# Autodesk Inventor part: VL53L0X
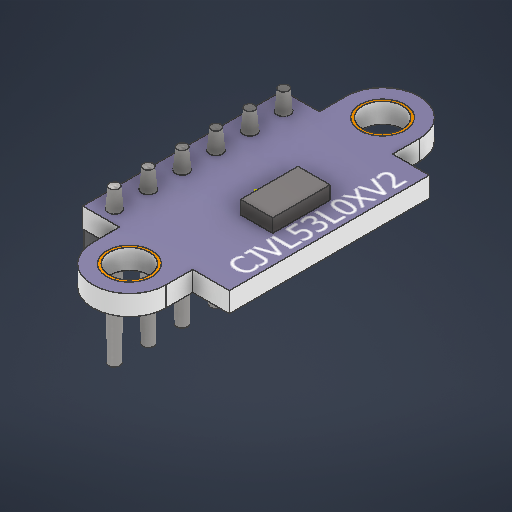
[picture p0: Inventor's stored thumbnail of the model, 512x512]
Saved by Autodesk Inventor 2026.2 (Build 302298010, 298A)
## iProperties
Created: 2026-04
Part Number: VL53L0X
Material: PPS 플라스틱
Document SubType Name: Modeling
Designer: work
Density: 1.637 g/cm^3
Appearance: 매끄러움 - 흰색
Author: work
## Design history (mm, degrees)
sketch "스케치1"
  geometry: L1 (-5.5, 7.5)-(5.5, 7.5); L2 (5.5, 7.5)-(5.5, -7.5); L3 (5.5, -7.5)-(-5.5, -7.5); L4 (-5.5, -7.5)-(-5.5, 7.5); L5 (-5.5, 7.5)-(5.5, -7.5); L6 (5.5, 7.5)-(-5.5, -7.5); L7 (0, 9.5)-(0, -9.5); L8 (0, 9.5)-(0, -9.5); L9 (-2.75, 9.5)-(-2.75, -9.5); L10 (2.75, -9.5)-(2.75, 9.5); C1 r 1.5 at (0, 9.5); C2 r 1.5 at (0, -9.5); A1 r 2.75 centre (0, 9.5) between (2.75, 9.5) and (-2.75, 9.5); A2 r 2.75 centre (0, -9.5) between (-2.75, -9.5) and (2.75, -9.5); 6 further points
  constraints: 22 end point, 6 midpoint, 4 centre point, 4 equal length, 4 point on circle, 4 tangent, 2 coincident, 1 horizontal, 1 perpendicular, 1 vertical
  dimensions: "d0" = 11 distance of L2.end L3.end; "d1" = 15 distance of L1.end L2.end; "d2" = 19 distance of L7.start L7.end; "d3" = 5.5 diameter of A2; "d4" = 3 diameter of C1; "d5" = 3 diameter of C2
extrude "돌출1" new body sketch "스케치1" distance "d6" = 1.5; taper "d7" = 0 deg
sketch "스케치2"
  geometry: L1 (5.5, -7.5)-(5.5, 7.5) reference; L2 (5.5, 0)-(-5.5, 0); L3 (-5.5, 7.5)-(-5.5, -7.5) reference; L4 (3.4, -2.15)-(1, -2.15); L5 (1, -2.15)-(1, 2.15); L6 (1, 2.15)-(3.4, 2.15); L7 (3.4, 2.15)-(3.4, -2.15); L8 (3.4, -2.15)-(1, 2.15); L9 (1, -2.15)-(3.4, 2.15); 2 further points
  constraints: 14 end point, 4 midpoint, 2 parallel, 1 horizontal, 1 perpendicular, 1 point on line
  dimensions: "d8" = 2.4 distance of L5.end L6.end; "d9" = 4.3 distance of L4.end L5.end; "d10" = 4.5 distance between parallel lines of L1 L5
extrude "돌출2" join sketch "스케치2" distance "d11" = 1; taper "d12" = 0 deg
sketch "스케치3"
  geometry: L1 (0, 0)-(-5.5, 0); L2 (-5.5, -7.5)-(-5.5, 7.5) reference; L3 (-3.1, 7.45)-(-5.5, 7.45); L4 (-5.5, 7.45)-(-5.5, -7.45); L5 (-5.5, -7.45)-(-3.1, -7.45); L6 (-3.1, -7.45)-(-3.1, 7.45); L7 (-3.1, 7.45)-(-5.5, -7.45); L8 (-5.5, 7.45)-(-3.1, -7.45); L9 (-5.45, -7.45)-(-5.45, 7.45); 2 further points
  constraints: 16 end point, 4 point on line, 3 midpoint, 2 parallel, 2 perpendicular, 1 horizontal
  dimensions: "d13" = 2.4 distance of L4.end L5.end; "d14" = 14.9 distance of L5.end L3.start; "d17" = 0.05 distance between parallel lines of L2 L9
extrude "돌출3" join sketch "스케치3" distance "d15" = 1.5; taper "d16" = 0 deg
sketch "스케치4"
  geometry: L1 (1, 2.15)-(3.4, 2.15) reference; L2 (3.4, 2.15)-(3.4, -2.15) reference; L3 (3.4, -2.15)-(1, -2.15) reference; L4 (1, -2.15)-(1, 2.15) reference; L5 (2.75, -9.5)-(2.75, -7.5) reference; L6 (2.75, -7.5)-(5.5, -7.5) reference; L7 (5.5, -7.5)-(5.5, 7.5) reference; L8 (5.5, 7.5)-(2.75, 7.5) reference; L9 (2.75, 7.5)-(2.75, 9.5) reference; L10 (-2.75, 9.5)-(-2.75, 7.5) reference; L11 (-2.75, 7.5)-(-5.5, 7.5) reference; L12 (-5.5, 7.5)-(-5.5, -7.5) reference; L13 (-5.5, -7.5)-(-2.75, -7.5) reference; L14 (-2.75, -7.5)-(-2.75, -9.5) reference; C1 r 1.5 at (0, 9.5) reference; C2 r 1.5 at (0, -9.5) reference; C3 r 1.7 at (0, 9.5); C4 r 1.7 at (0, -9.5); A1 r 2.75 centre (0, -9.5) between (-2.75, -9.5) and (2.75, -9.5) reference; A2 r 2.75 centre (0, 9.5) between (2.75, 9.5) and (-2.75, 9.5) reference; 1 further point
  constraints: 2 centre point, 2 coincident
  dimensions: "d18" = 0.2 radial gap between concentric circles of C3 C1; "d19" = 0.2 radial gap between concentric circles of C4 C2
feature "표식1" sketch "스케치4"
sketch "스케치5"
  geometry: L1 (-3.1, 2.05)-(-3.1, 16.95) reference; L2 (-5.5, 2)-(-2.75, 2) reference; L3 (-4.125, 2)-(-4.125, 17); L4 (-2.75, 17)-(-5.5, 17) reference; C1 r 0.5 at (-4.125, 3); C2 r 0.5 at (-4.125, 5.54); C3 r 0.5 at (-4.125, 8.08); C4 r 0.5 at (-4.125, 10.62); C5 r 0.5 at (-4.125, 13.16); C6 r 0.5 at (-4.125, 15.7); 1 further point
  constraints: 6 centre point, 2 end point, 2 midpoint, 1 point on line, 1 vertical, 10 other
  dimensions: "d20" = 1 distance from line of L2 C1.centre; "d23" = 2.54 distance of C1.centre C2.centre; "d28" = 1 diameter of C1
  node "스케치 - 직사각형 패턴1" dims "d23" = 2.54, "d26" = 10
extrude "돌출4" join sketch "스케치5" distance "d29" = 1.5; taper "d30" = -5 deg
extrude "돌출5" join sketch "스케치5" distance "d31" = 10; taper "d32" = -0.5 deg
sketch "스케치6" dims "d0" = 11, "d1" = 15, "d2" = 19, "d3" = 5.5, "d4" = 3, "d5" = 3
  geometry: L1 (3.571, 3.54)-(3.571, 15.852); L2 (3.571, 15.852)-(5.134, 15.852); L3 (5.134, 15.852)-(5.134, 3.54); L4 (5.134, 3.54)-(3.571, 3.54); 1 further point
  constraints: 2 other
node "솔리드1"
node "투영된 루프1"
